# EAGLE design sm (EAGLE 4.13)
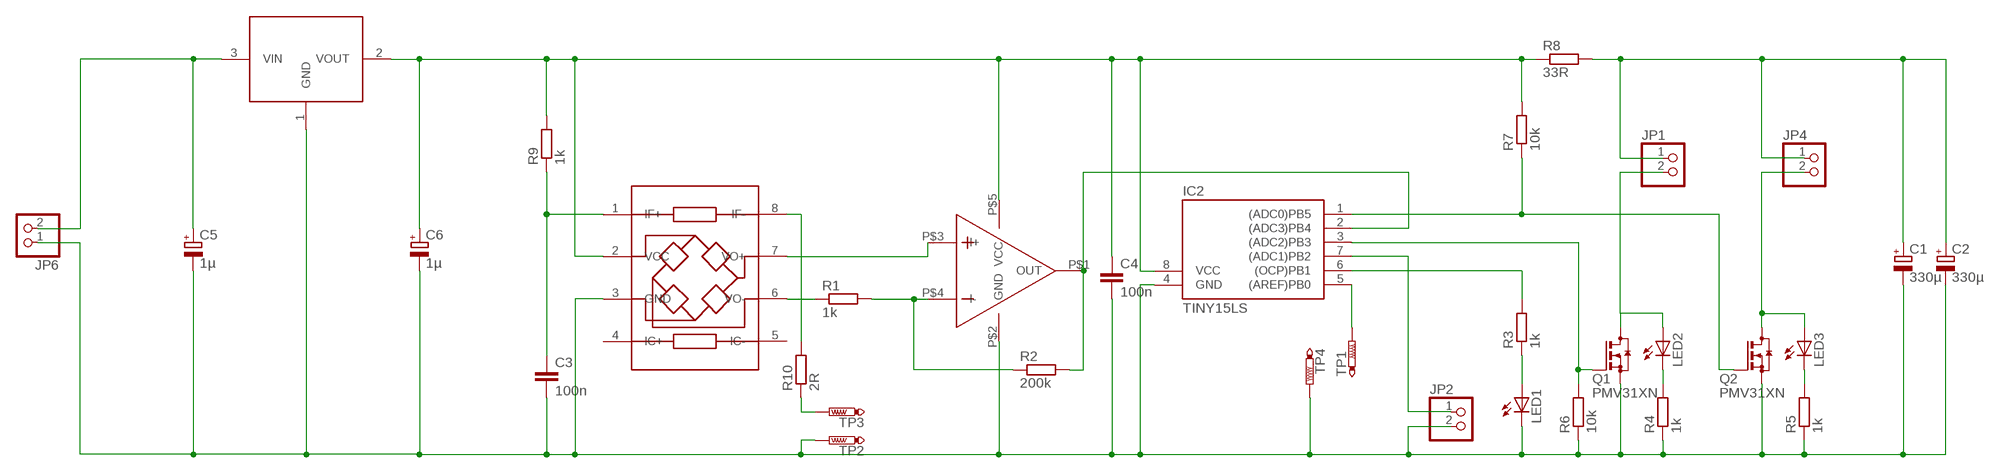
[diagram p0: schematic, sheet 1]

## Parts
C1  330µ  CPOL-EUE3.5-8  [E3,5-8]
C2  330µ  CPOL-EUE3.5-8  [E3,5-8]
C3  100n  C-EUC0805  [C0805]
C4  100n  C-EUC0805  [C0805]
C5  1µ  CPOL-EUA  [PANASONIC_A]
C6  1µ  CPOL-EUA  [PANASONIC_A]
IC1  XC62FP5002  [SOT23]
IC2  TINY15LS  [SOIC8]
IC3  KMZ51  [SO08]
IC4  MCP6001  [SOT23-5]
JP1  PINHD-1X2  [1X02]
JP2  PINHD-1X2  [1X02]
JP4  PINHD-1X2  [1X02]
JP6  PINHD-1X2  [1X02]
LED1  LEDCHIPLED_0805  [CHIPLED_0805]
LED2  LEDCHIPLED_0805  [CHIPLED_0805]
LED3  LEDCHIPLED_0805  [CHIPLED_0805]
Q1  PMV31XN  [SOT23]
Q2  PMV31XN  [SOT23]
R1  1k  R-EU_R0805  [R0805]
R2  200k  R-EU_R0805  [R0805]
R3  1k  R-EU_R0805  [R0805]
R4  1k  R-EU_R0805  [R0805]
R5  1k  R-EU_R0805  [R0805]
R6  10k  R-EU_R0805  [R0805]
R7  10k  R-EU_R0805  [R0805]
R8  33R  R-EU_R0805  [R0805]
R9  1k  R-EU_R0805  [R0805]
R10  2R  R-EU_R0805  [R0805]
TP1  PTR1TP10SQ  [TP10SQ]
TP2  PTR1TP10SQ  [TP10SQ]
TP3  PTR1TP10SQ  [TP10SQ]
TP4  PTR1TP10SQ  [TP10SQ]

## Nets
GND: C1.- C2.- C3.2 C4.2 C5.- C6.- IC1.1(GND) IC2.4(GND) IC3.3(GND) IC4.P$2(GND) JP2.2 JP6.1 LED1.C Q1.2(S) Q2.2(S) R4.1 R5.1 R6.1 TP2.TP TP4.TP
N$1: IC3.7(VO+) IC4.P$3(I+)
N$2: IC3.6(VO-) R1.1
N$3: IC4.P$4(I-) R1.2 R2.1
N$4: IC2.2((ADC3)PB4) IC4.P$1(OUT) R2.2
N$5: LED1.A R3.1
N$6: IC2.6((OCP)PB1) R3.2
N$7: IC2.5((AREF)PB0) TP1.TP
N$8: R10.1 TP3.TP
N$9: IC2.7((ADC1)PB2) JP2.1
N$10: LED2.C R4.2
N$11: IC2.1((ADC0)PB5) Q2.1(G) R7.1
N$12: LED3.C R5.2
N$13: IC2.3((ADC2)PB3) Q1.1(G) R6.2
N$14: JP1.2 LED2.A Q1.3(D)
N$15: JP4.2 LED3.A Q2.3(D)
N$17: IC3.8(IF-) R10.2
N$18: C1.+ C2.+ JP1.1 JP4.1 R8.2
N$19: C3.1 IC3.1(IF+) R9.1
VCC: C4.1 C6.+ IC1.2(VOUT) IC2.8(VCC) IC3.2(VCC) IC4.P$5(VCC) R7.2 R8.1 R9.2
VIN: C5.+ IC1.3(VIN) JP6.2
Unconnected: IC3.4(IC+) IC3.5(IC-)

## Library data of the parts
C1 C2 C5 C6 = rcl:CPOL-EU: POLARIZED CAPACITOR, European symbol
C3 C4 = rcl:C-EU: CAPACITOR, European symbol
IC1 = 0mylib:XC62FP5002
IC2 = atmel:TINY15L: MICROCONTROLLER 2.7 V 1 Kbytes FLASH 64 bytes EEPROM 4-channel 10 bit ADC
IC3 = 0mylib:KMZ51
IC4 = 0mylib:MCP6001
JP1 JP2 JP4 JP6 = pinhead:PINHD-1X2: PIN HEADER
LED1-LED3 = led:LED: LED
Q1 Q2 = 0mylib:PMV31XN: N-CHANNEL MOS FET
R1-R10 = rcl:R-EU_: RESISTOR, European symbol
TP1-TP4 = testpad:PTR1: TEST PIN

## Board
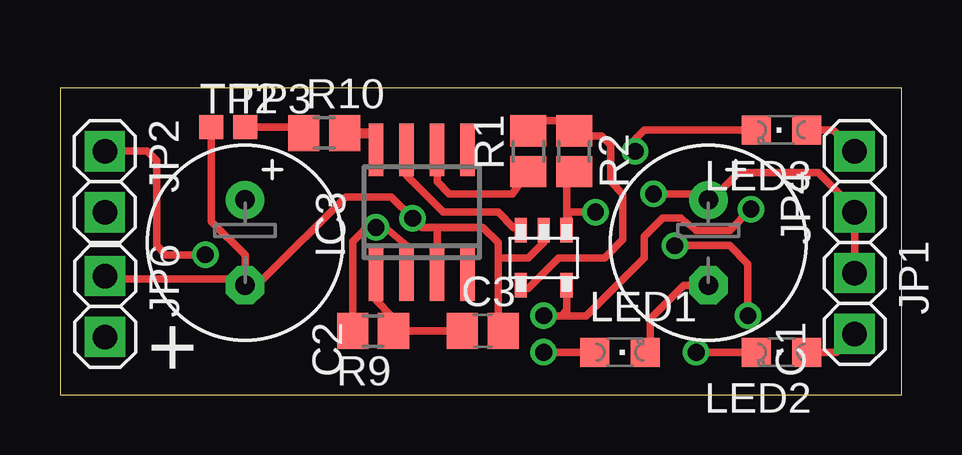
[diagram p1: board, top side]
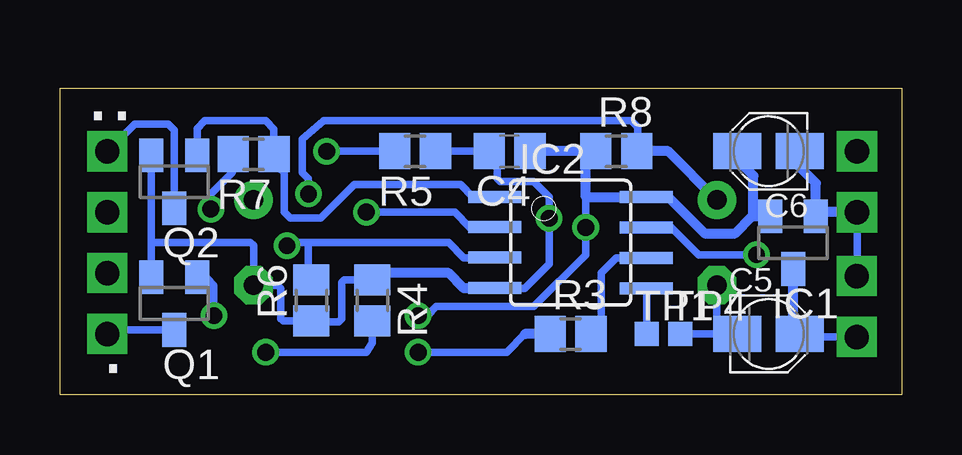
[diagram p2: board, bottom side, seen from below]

Size 35.08 x 12.79 mm. Coordinates in mm from the lower left corner, seen from the top.
Outline: 0,0 35.08,0 35.08,12.79 0,12.79 0,0
Copper layers (1*16): Top 0.035mm / dielectric 1.5mm / Bottom 0.035mm
Design rules "default": minimum track width 10mil, minimum drill 24mil, track to track 8mil, track to pad 8mil, pad to pad 8mil, via to via 8mil, smd to smd 8mil, copper to edge 40mil, drill to drill 8mil, minimum pad ring 10mil, minimum via ring 8mil, stop-mask expansion 4mil, vias tented up to drill 0mil, thermal gap 10mil

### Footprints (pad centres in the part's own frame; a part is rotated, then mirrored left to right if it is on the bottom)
E3,5-8 = drill 0.813 pad 1.6 round: + -1.778,0 | drill 0.813 pad 1.6 octagon: - 1.778,0
C0805 = smd 1.3 x 1.5: 1 -0.85,0; 2 0.85,0
PANASONIC_A = smd 2 x 1.5: + 1.3,0; - -1.3,0
SOT23 = smd 1 x 1.4: 1 -0.95,-1.1; 2 0.95,-1.1; 3 0,1.1
SOIC8 = smd 0.5 x 2.2: 1 -1.905,-3.154; 2 -0.645,-3.154; 3 0.625,-3.154; 4 1.895,-3.154; 5 1.905,3.154; 6 0.635,3.154; 7 -0.635,3.154; 8 -1.905,3.154
SO08 = smd 0.6 x 2.2: 1 -1.905,-2.6; 2 -0.635,-2.6; 3 0.635,-2.6; 4 1.905,-2.6; 5 1.905,2.6; 6 0.635,2.6; 7 -0.635,2.6; 8 -1.905,2.6
SOT23-5 = smd 1.016 x 0.508: P$1 -1.143,0.953; P$2 -1.143,0; P$3 -1.143,-0.953; P$4 1.143,-0.953; P$5 1.143,0.953
1X02 = drill 1.016 pad 1.676 square: 1 -1.27,0; 2 1.27,0
CHIPLED_0805 = smd 1.2 x 1.2: A 0,-1.05; C 0,1.05
R0805 = smd 1.3 x 1.5: 1 -0.85,0; 2 0.85,0
TP10SQ = smd 1 x 1: TP 0,0

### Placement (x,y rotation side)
C1  27.01,6.34 270 top
C2  7.71,6.34 270 top
C3  17.62,2.66 0 top
C4  16.35,10.16 180 bottom
C5  5.55,2.54 0 bottom
C6  5.55,10.16 180 bottom
IC1  4.53,6.34 180 bottom
IC2  13.81,6.34 270 bottom
IC3  15.08,7.61 0 top
IC4  20.16,5.71 270 top
JP1  33.11,3.8 270 top
JP2  1.87,8.88 270 top
JP4  33.11,8.88 90 top
JP6  1.88,3.68 270 top
LED1  23.33,1.77 270 top
LED2  30.06,1.77 90 top
LED3  30.06,11.04 90 top
Q1  30.32,3.8 180 bottom
Q2  30.32,8.88 180 bottom
R1  19.52,10.16 90 top
R2  21.43,10.16 270 top
R3  13.81,2.54 0 bottom
R4  22.06,3.93 270 bottom
R5  20.28,10.16 180 bottom
R6  24.6,3.93 90 bottom
R7  27.01,10.03 180 bottom
R8  11.9,10.16 0 bottom
R9  13.04,2.66 180 top
R10  11.01,10.92 0 top
TP1  10.63,2.54 0 bottom
TP2  6.31,11.17 0 top
TP3  7.71,11.17 0 top
TP4  9.23,2.54 0 bottom

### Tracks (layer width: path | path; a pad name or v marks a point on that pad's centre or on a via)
GND  (via drill 0.7)
  Top 0.305: C3.2 18.25,2.75 18.25,5.71 | 18.25,5.71 18.25,6.34 17.62,6.98 15.71,6.98 | IC4.P$2 20.16,6.34 19.52,5.71 18.25,5.71 | 15.71,6.98 IC3.3 | 24.6,2.12 24.6,3.17 26,4.57 C1.- | 15.71,6.98 15.08,6.98 v14.69,7.36 13.81,8.25 11.9,8.25 8.47,4.82 7.71,4.82 | JP6.1 1.99,4.82 7.71,4.82 | 7.71,4.82 7.71,4.69 7.71,5.84 6.31,7.23 TP2.TP
  Top 0.406: 24.6,2.12 LED1.C | 7.71,4.69 C2.-
  Bottom 0.305: C2.- 7.71,2.54 TP4.TP | 16.98,4.44 15.71,4.44 14.69,5.46 v14.69,7.36 14.69,8.25 15.33,8.88 16.73,8.88 16.85,9.01 16.85,9.81 C4.2 | 30.95,9.52 30.95,10.16 31.1,10.16 Q2.2 31.25,9.99 | C4.2 17.11,10.16 | C4.2 R5.1 | R4.1 23.24,4.78 23.33,4.69 23.33,3.17 23.46,3.04 24.6,3.04 R6.1 25.78,3.08 25.87,3.17 25.87,4.44 26,4.57 C1.- 27.01,6.22 27.14,6.34 31.27,6.34 | JP6.1 JP2.2 | 31.25,9.99 31.2,10.03 | 31.27,6.34 Q1.2 | 31.27,6.34 31.27,9.97 31.25,9.99
  Bottom 0.406: 6.82,2.54 C5.- 7.71,2.54 | C6.- 4.28,10.16 4.28,9.52 3.58,8.82 IC1.1 3.16,7.61 JP2.2 | R4.1 21.85,5.08 18.89,5.08 18.25,4.44 16.98,4.44 16.97,4.44 IC2.4
N$1
  Top 0.305: IC4.P$3 19.08,6.98 18.89,6.98 18.25,7.61 15.96,7.61 14.44,9.14 IC3.7
N$2
  Top 0.305: IC3.6 15.71,8.88 16.22,8.38 18.85,8.38 R1.1
N$3
  Top 0.305: R2.1 21.64,10.79 22.57,10.79 22.95,10.41 22.95,8.88 23.46,8.38 23.46,6.47 22.7,5.71 20.79,5.71 19.52,4.44 19.33,4.44 IC4.P$4 | 21.43,11.43 19.94,11.43
  Top 0.406: R2.1 21.43,11.43 | 19.94,11.43 R1.2
N$4  (via drill 0.7 pad 0.3)
  Top 0.305: 21.17,9.2 R2.2 21.43,9.39 21.11,9.08 IC4.P$1 21.17,6.85 21.17,7.61 v22.31,7.61
  Bottom 0.305: IC2.2 16.97,6.98 18,6.98 18.63,7.61 v22.31,7.61
N$5  (via drill 0.7)
  Top 0.305: v20.16,1.77 LED1.A
  Bottom 0.305: v20.16,1.77 16.47,1.77 15.71,2.54
  Bottom 0.406: 14.44,2.54 R3.1 15.71,2.54
N$6
  Bottom 0.305: IC2.6 11.9,5.71 12.54,5.08 12.54,2.54
  Bottom 0.406: R3.2 12.54,2.54
N$7
  Bottom 0.305: TP1.TP 10.63,4.44
  Bottom 0.406: 10.63,4.44 IC2.5
N$8
  Top 0.305: TP3.TP 10,11.17
  Top 0.406: R10.1 10.25,10.92 10,11.17
N$9  (via drill 0.7)
  Top 0.305: v6.06,5.84 4.41,5.84 4.03,6.22 4.03,9.77 3.65,10.16 JP2.1
  Bottom 0.305: IC2.7 9.61,6.98 8.47,5.84 v6.06,5.84
N$10  (via drill 0.7)
  Top 0.305: v26.51,1.77 LED2.C
  Bottom 0.305: R4.2 22.06,2.15 22.31,1.77 v26.51,1.77
N$11
  Bottom 0.305: IC2.1 17.87,8.25 18.38,8.76 22.82,8.76 24.22,7.36 25.49,7.36 25.74,7.61 25.74,9.27 25.93,9.46 | Q2.1 29.37,11.11 29.05,11.43 26.51,11.43 26.16,11.08 R7.1 | 25.93,9.46 26.16,9.69 | R7.1 26.16,9.81 26.12,9.77 | 26.38,10.03 R7.1 | 26.38,10.03 26.51,10.16 | 25.93,9.46 25.87,9.52 26.38,10.03
N$12  (via drill 0.7 pad 0.3)
  Top 0.305: v23.96,10.16 23.96,10.66 24.35,11.04 LED3.C
  Bottom 0.305: R5.2 v23.96,10.16
N$13  (via drill 0.7)
  Top 0.305: v28.66,3.3 28.66,5.46 27.9,6.22 v25.62,6.22
  Bottom 0.305: 16.97,5.71 18.25,5.71 18.89,6.34 24.73,6.34 | R6.2 24.69,4.78 24.73,5.08 24.73,6.34 | v28.66,3.3 28.66,4.57 28.92,4.82 29.3,4.82 29.37,4.89 Q1.1 | v25.62,6.22 25.49,6.34 24.73,6.34
  Bottom 0.406: IC2.3 16.97,5.71
N$14
  Top 0.305: LED2.A 32.35,1.77 JP1.2
  Bottom 0.305: Q1.3 32.94,2.71 JP1.2
N$15
  Top 0.305: 31.2,11.04 LED3.A 32.22,11.04 JP4.2
  Bottom 0.305: 30.48,7.61 Q2.3 30.32,11.04 30.57,11.3 31.97,11.3 JP4.2
N$17
  Top 0.305: 13.17,10.16 IC3.8 13.17,10.79
  Top 0.406: R10.2 13.04,10.92 13.17,10.79
N$18  (via drill 0.7)
  Top 0.305: v24.73,8.38 26.76,8.38 C1.+ 27.14,8.12 28.28,9.27 31.59,9.27 33.11,7.74 JP1.1 JP4.1
  Bottom 0.305: v24.73,8.38 24.73,9.01 24.98,9.27 24.98,10.66 24.09,11.43 11.27,11.43 11.01,11.17 11.01,10.16
  Bottom 0.406: C2.+ 9.74,10.16 11.01,10.16 R8.2
N$19
  Top 0.305: C3.1 R9.1 13.81,2.66 13.81,3.3 13.17,3.93 IC3.1
VCC  (via drill 0.7)
  Top 0.305: IC3.2 14.44,6.22 13.55,6.98 v13.17,6.98 12.79,6.98 12.19,6.38 R9.2 | v20.16,3.3 20.92,3.3 21.11,3.55 IC4.P$5 21.11,3.36 21.04,3.3 21.93,3.3 24.35,5.71 24.35,6.6 25.11,7.36 25.87,7.36 26.51,6.85 27.9,6.85 v28.79,7.74
  Bottom 0.305: 13.17,8.25 v13.17,6.98 13.17,5.84 15.33,3.68 19.39,3.68 19.77,3.3 v20.16,3.3 | v28.79,7.74 28.79,8.38 27.9,9.27 27.9,10.03 R7.2
  Bottom 0.406: 15.71,10.16 C4.1 13.17,10.16 | 13.17,10.16 R8.1 | 13.17,10.16 13.17,8.25 IC2.8 9.74,8.25 8.22,6.73 6.95,6.73 6.23,7.44 6.18,7.44 | 6.18,7.44 IC1.2 | C6.+ 6.85,9.8 6.18,9.14 6.18,7.44
VIN
  Bottom 0.305: JP6.2 4.16,2.41 4.28,2.54
  Bottom 0.406: C5.+ 4.28,2.54 4.28,2.66 4.53,2.92 IC1.3

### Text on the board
Top: +
Bottom: .. | .
tPlace: +
bPlace: .. | .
